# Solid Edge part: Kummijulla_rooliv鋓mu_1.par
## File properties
Author: KULL
Template: Iso Metric Part.par
Last saved by: KULL
Revision: 5
Application: Solid Edge
Accuracy: 0,990
Face Style: Model Default
Fill Style: Normal
Coef. of Thermal Exp: 0.0
Thermal Conductivity: 0.0
Specific Heat: 0.0
Modulus of Elasticity: 0.0
Poisson's Ratio: 0.0
Yield Stress: 0.0
Ultimate Stress: 0.0
Elongation: 0.0
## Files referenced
..\..\Rover_ASM.asm
D:\Solid edge leong\Solid edge Sync practice\ROVER_Heiko_Kull_EKSAM\Roolimise_jupid\Roolivõimu silinder.par
D:\Solid edge leong\Solid edge Sync practice\ROVER_Heiko_Kull_EKSAM\Roolimise_jupid\Roolivõimu silindri varras.par
imu silinder.par
imu silindri varras.par
QD:\Solid edge leong\Solid edge Sync practice\ROVER_Heiko_Kull_EKSAM\Rover_ASM.asm
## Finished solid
Body 1: sheet body, 2 faces, 3 edges, 0 vertices.
  Faces by surface: cylinder 1, plane 1
  Edges by curve: circle 3
Body 2: solid body, 10 faces, 10 edges, 0 vertices.
  Faces by surface: cylinder 4, plane 2, spun 2, torus 2
  Edges by curve: circle 10
Body 3: sheet body, 1 face, 2 edges, 0 vertices.
  Faces by surface: cylinder 1
  Edges by curve: circle 2
Bounding box of the edges (mm; curved faces can reach further): 8.000 x 115.528 x 8.000, from (-26, -57.7639, 16.8206) to (-18, 57.7639, 24.8206).
Cylindrical faces by radius (mm): R2 x2, R2.5 x1, R3 x2, R4 x1
Toroidal faces (ring radius, tube radius in mm): R2.2 r0.3 x1, R3.7 r0.3 x1
Planar faces by outward normal: +y 1, -y 1
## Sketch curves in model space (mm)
line (-22, 49.7788, 20.8206) -> (-22, 32.0261, 20.8206)
circle centre (-22, 36, 20.8206) radius 4
circle centre (-22, 36, 20.8206) radius 3
circle centre (-22, 49.7788, 20.8206) radius 2
circle centre (-22, 49.7788, 20.8206) radius 2.5
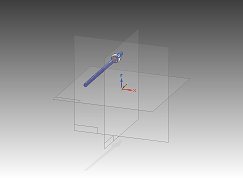
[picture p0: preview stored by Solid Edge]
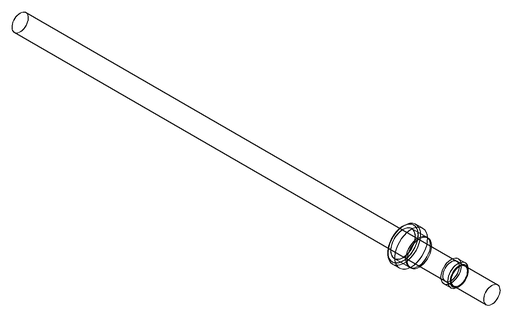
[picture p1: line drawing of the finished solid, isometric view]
